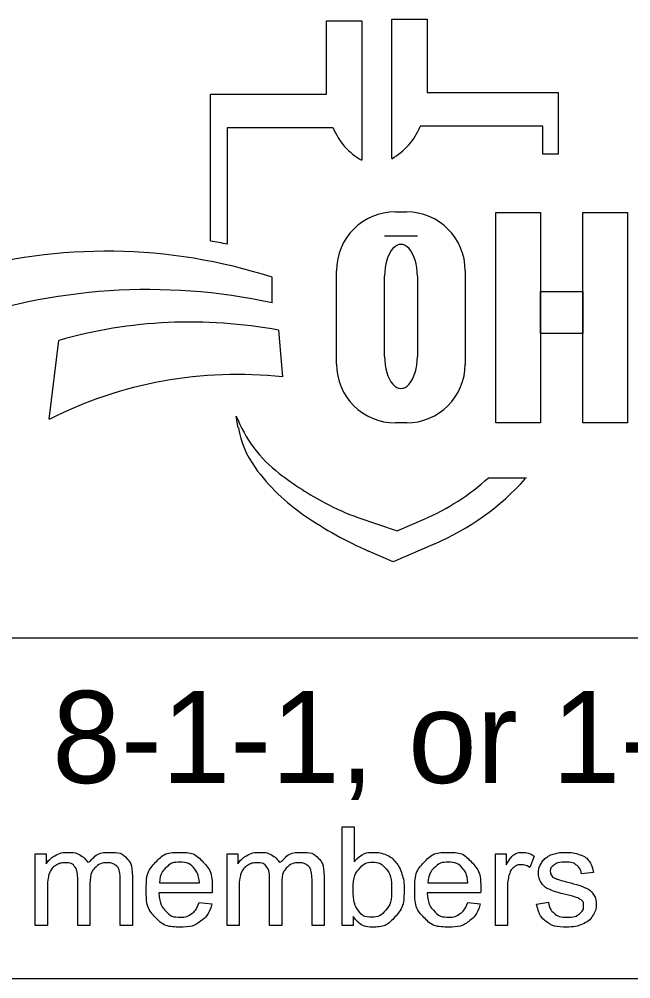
# Model space of a CAD drawing. Extents: x -17.5 to 72.9, y -57.8 to 32.3.
# Drawn here: x -6.937 to -6.007, y 1.809 to 3.269 of the extents above; entities that cross this region are included whole.
import ezdxf

# ---------------------------------------------------------------- set-up
doc = ezdxf.new("R2010")
doc.units = 0
doc.layers.add('SH_Data', color=7, linetype='Continuous')
doc.layers.add('SH_Text', color=7, linetype='Continuous')

msp = doc.modelspace()

# ---------------------------------------------------------------- linework, layer by layer
at = {"layer": 'SH_Data'}
for p, q in [((-3.5759, 2.3272), (-7.8259, 2.3272)), ((-3.5759, 1.8094), (-7.8259, 1.8094))]:
    msp.add_line(p, q, dxfattribs=at)
at = {"layer": 'SH_Text'}
for p, q in [((-6.4699, 3.1549), (-6.4699, 3.2664)), ((-6.4699, 3.2664), (-6.4162, 3.2664)), ((-6.4162, 3.2664), (-6.4162, 3.0543)), ((-6.3705, 3.0566), (-6.3705, 3.2687)), ((-6.3705, 3.2687), (-6.3169, 3.2687)), ((-6.3169, 3.2687), (-6.3169, 3.1572)), ((-6.6458, 2.931), (-6.6458, 3.1549)), ((-6.6458, 3.1549), (-6.4699, 3.1549)), ((-6.3169, 3.1572), (-6.1177, 3.1572)), ((-6.1177, 3.1572), (-6.1177, 3.0634)), ((-6.6206, 3.1034), (-6.6206, 2.9266)), ((-6.4594, 3.1034), (-6.6206, 3.1034)), ((-6.1409, 3.1058), (-6.3273, 3.1058)), ((-6.1409, 3.0634), (-6.1409, 3.1058)), ((-6.1177, 3.0634), (-6.1409, 3.0634)), ((-6.3649, 2.9757), (-6.3483, 2.9757)), ((-6.3316, 2.9387), (-6.3814, 2.9387)), ((-6.5525, 2.8763), (-6.5525, 2.8375)), ((-6.4543, 2.7442), (-6.4543, 2.8862)), ((-6.3814, 2.7556), (-6.3814, 2.8779)), ((-6.3316, 2.8779), (-6.3316, 2.7556)), ((-6.2589, 2.8862), (-6.2589, 2.7442)), ((-6.5426, 2.7957), (-6.5363, 2.7248)), ((-6.8914, 2.6602), (-6.8767, 2.7803)), ((-6.6037, 2.6473), (-6.6067, 2.6652)), ((-6.3483, 2.6547), (-6.3649, 2.6547)), ((-6.2234, 2.5714), (-6.1659, 2.5714)), ((-6.4218, 2.511), (-6.3624, 2.4905)), ((-6.3624, 2.4905), (-6.3213, 2.5083)), ((-6.3051, 2.471), (-6.3684, 2.4435)), ((-6.3684, 2.4435), (-6.4058, 2.4599))]:
    msp.add_line(p, q, dxfattribs=at)
for points in [[(-6.2124, 2.9746), (-6.1445, 2.9746), (-6.1445, 2.6547), (-6.2124, 2.6547)], [(-6.0803, 2.9746), (-6.0123, 2.9746), (-6.0123, 2.6547), (-6.0803, 2.6547)], [(-6.1445, 2.8548), (-6.0803, 2.8548), (-6.0803, 2.7908), (-6.1445, 2.7908)]]:
    msp.add_lwpolyline(points, close=True, dxfattribs=at)
for points in [[(-6.4291, 1.8905), (-6.4461, 1.8905), (-6.4461, 2.0407), (-6.4277, 2.0407), (-6.4277, 1.9871)], [(-6.9122, 1.8905), (-6.9122, 1.9993), (-6.8957, 1.9993), (-6.8957, 1.984)], [(-6.6208, 1.8905), (-6.6208, 1.9993), (-6.6043, 1.9993), (-6.6043, 1.984)], [(-6.213, 1.8905), (-6.213, 1.9993), (-6.1964, 1.9993), (-6.1964, 1.9828)], [(-6.1539, 1.9959), (-6.1604, 1.9788)], [(-6.064, 1.9712), (-6.0821, 1.9688)], [(-6.8291, 1.9537), (-6.8291, 1.8905), (-6.8475, 1.8905), (-6.8475, 1.9611)], [(-6.7646, 1.9652), (-6.7646, 1.8905), (-6.7831, 1.8905), (-6.7831, 1.959)], [(-6.5377, 1.9537), (-6.5377, 1.8905), (-6.5561, 1.8905), (-6.5561, 1.9611)], [(-6.4733, 1.9652), (-6.4733, 1.8905), (-6.4917, 1.8905), (-6.4917, 1.959)], [(-6.8937, 1.9469), (-6.8937, 1.8905), (-6.9122, 1.8905)], [(-6.7235, 1.9553), (-6.6628, 1.9553)], [(-6.6024, 1.9469), (-6.6024, 1.8905), (-6.6208, 1.8905)], [(-6.3155, 1.9553), (-6.2548, 1.9553)], [(-6.1946, 1.9475), (-6.1946, 1.8905), (-6.213, 1.8905)], [(-6.6434, 1.9402), (-6.7246, 1.9402)], [(-6.2354, 1.9402), (-6.3166, 1.9402)], [(-6.663, 1.9256), (-6.6439, 1.9232)], [(-6.255, 1.9256), (-6.2359, 1.9232)], [(-6.1504, 1.923), (-6.1322, 1.9259)], [(-6.4291, 1.9041), (-6.4291, 1.8905)]]:
    msp.add_lwpolyline(points, dxfattribs=at)
for centre, radius, start, end in [((-6.3681, 3.1402), 0.0985, 201.9296, 240.7469), ((-6.4187, 3.1425), 0.0985, 299.2531, 338.0704), ((-6.3649, 2.8862), 0.0895, 90, 180), ((-6.3483, 2.8862), 0.0895, 0, 90), ((-6.7739, 2.122), 0.8191, 79.2074, 81.0007), ((-6.8037, 2.0967), 0.8191, 72.1402, 106.3144), ((-6.7406, 1.9656), 0.8919, 77.8238, 109.8274), ((-6.6767, 2.0759), 0.7322, 79.44, 105.8467), ((-6.3649, 2.7442), 0.0895, 180, 270), ((-6.3483, 2.7442), 0.0895, 270, 0), ((-6.6047, 2.0927), 0.6357, 83.8248, 116.8021), ((-6.4193, 2.7373), 0.2008, 201.0457, 232.5314), ((-6.4624, 2.6714), 0.1433, 189.6817, 216.0884), ((-6.3287, 2.7688), 0.3088, 216.0884, 235.7167), ((-6.2268, 2.9885), 0.5173, 232.5314, 241.794), ((-6.4647, 2.8388), 0.3602, 293.4582, 312.0712), ((-6.4647, 2.8388), 0.401, 293.4582, 317.8286), ((-6.312, 2.8297), 0.3371, 241.794, 250.9821), ((-6.1622, 3.013), 0.6044, 235.7167, 246.2325)]:
    msp.add_arc(centre, radius, start, end, dxfattribs=at)
for centre, start_param, end_param in [((-6.3565, 2.8779), 4.712389, 7.853982), ((-6.3565, 2.7556), 1.570796, 4.712389)]:
    msp.add_ellipse(centre, major_axis=(0, 0.0484), ratio=0.514403, start_param=start_param, end_param=end_param, dxfattribs=at)
for points in [[(-6.8957, 1.984), (-6.8905, 1.992), (-6.882, 1.9969), (-6.8735, 2.0017), (-6.8627, 2.0017), (-6.8506, 2.0017), (-6.8428, 1.9967), (-6.8351, 1.9917), (-6.8319, 1.9826), (-6.819, 2.0017), (-6.7983, 2.0017), (-6.7821, 2.0017), (-6.7734, 1.9928), (-6.7646, 1.9838), (-6.7646, 1.9652)], [(-6.6439, 1.9232), (-6.6484, 1.9065), (-6.6606, 1.8973), (-6.6728, 1.8881), (-6.6917, 1.8881), (-6.7156, 1.8881), (-6.7296, 1.9028), (-6.7436, 1.9175), (-6.7436, 1.944), (-6.7436, 1.9714), (-6.7294, 1.9866), (-6.7153, 2.0017), (-6.6928, 2.0017), (-6.671, 2.0017), (-6.6571, 1.9869), (-6.6433, 1.972), (-6.6433, 1.9451), (-6.6433, 1.9435), (-6.6434, 1.9402)], [(-6.6043, 1.984), (-6.5992, 1.992), (-6.5907, 1.9969), (-6.5822, 2.0017), (-6.5713, 2.0017), (-6.5592, 2.0017), (-6.5515, 1.9967), (-6.5437, 1.9917), (-6.5406, 1.9826), (-6.5276, 2.0017), (-6.5069, 2.0017), (-6.4907, 2.0017), (-6.482, 1.9928), (-6.4733, 1.9838), (-6.4733, 1.9652)], [(-6.4277, 1.9871), (-6.416, 2.0017), (-6.3979, 2.0017), (-6.3879, 2.0017), (-6.3789, 1.9977), (-6.3699, 1.9937), (-6.3642, 1.9863), (-6.3584, 1.979), (-6.3551, 1.9687), (-6.3518, 1.9583), (-6.3518, 1.9466), (-6.3518, 1.9186), (-6.3656, 1.9034), (-6.3795, 1.8881), (-6.3988, 1.8881), (-6.4181, 1.8881), (-6.4291, 1.9041)], [(-6.2359, 1.9232), (-6.2404, 1.9065), (-6.2526, 1.8973), (-6.2648, 1.8881), (-6.2837, 1.8881), (-6.3076, 1.8881), (-6.3216, 1.9028), (-6.3356, 1.9175), (-6.3356, 1.944), (-6.3356, 1.9714), (-6.3214, 1.9866), (-6.3073, 2.0017), (-6.2848, 2.0017), (-6.263, 2.0017), (-6.2491, 1.9869), (-6.2353, 1.972), (-6.2353, 1.9451), (-6.2353, 1.9435), (-6.2354, 1.9402)], [(-6.1964, 1.9828), (-6.1901, 1.9944), (-6.1847, 1.9981), (-6.1793, 2.0017), (-6.1729, 2.0017), (-6.1636, 2.0017), (-6.1539, 1.9959)], [(-6.1322, 1.9259), (-6.1307, 1.9149), (-6.1236, 1.9091), (-6.1166, 1.9032), (-6.1039, 1.9032), (-6.0912, 1.9032), (-6.085, 1.9084), (-6.0789, 1.9136), (-6.0789, 1.9205), (-6.0789, 1.9268), (-6.0843, 1.9304), (-6.0881, 1.9329), (-6.1032, 1.9367), (-6.1235, 1.9418), (-6.1314, 1.9455), (-6.1392, 1.9492), (-6.1433, 1.9558), (-6.1473, 1.9624), (-6.1473, 1.9704), (-6.1473, 1.9777), (-6.144, 1.9839), (-6.1406, 1.9901), (-6.1349, 1.9942), (-6.1306, 1.9973), (-6.1231, 1.9995), (-6.1157, 2.0017), (-6.1072, 2.0017), (-6.0944, 2.0017), (-6.0847, 1.9981), (-6.075, 1.9944), (-6.0704, 1.9881), (-6.0657, 1.9817), (-6.064, 1.9712)], [(-6.8475, 1.9611), (-6.8475, 1.9734), (-6.852, 1.9796), (-6.8565, 1.9857), (-6.8668, 1.9857), (-6.8746, 1.9857), (-6.8812, 1.9816), (-6.8878, 1.9775), (-6.8908, 1.9696), (-6.8937, 1.9618), (-6.8937, 1.9469)], [(-6.7831, 1.959), (-6.7831, 1.9701), (-6.7849, 1.9749), (-6.7866, 1.9798), (-6.7914, 1.9828), (-6.7961, 1.9857), (-6.8024, 1.9857), (-6.8139, 1.9857), (-6.8215, 1.9781), (-6.8291, 1.9705), (-6.8291, 1.9537)], [(-6.6628, 1.9553), (-6.664, 1.9691), (-6.6697, 1.9759), (-6.6785, 1.9866), (-6.6926, 1.9866), (-6.7053, 1.9866), (-6.7139, 1.9781), (-6.7226, 1.9696), (-6.7235, 1.9553)], [(-6.5561, 1.9611), (-6.5561, 1.9734), (-6.5606, 1.9796), (-6.5651, 1.9857), (-6.5754, 1.9857), (-6.5832, 1.9857), (-6.5898, 1.9816), (-6.5964, 1.9775), (-6.5994, 1.9696), (-6.6024, 1.9618), (-6.6024, 1.9469)], [(-6.4917, 1.959), (-6.4917, 1.9701), (-6.4935, 1.9749), (-6.4953, 1.9798), (-6.5, 1.9828), (-6.5047, 1.9857), (-6.5111, 1.9857), (-6.5225, 1.9857), (-6.5301, 1.9781), (-6.5377, 1.9705), (-6.5377, 1.9537)], [(-6.4293, 1.9457), (-6.4293, 1.9262), (-6.424, 1.9175), (-6.4153, 1.9032), (-6.4005, 1.9032), (-6.3884, 1.9032), (-6.3796, 1.9137), (-6.3708, 1.9242), (-6.3708, 1.945), (-6.3708, 1.9663), (-6.3792, 1.9765), (-6.3877, 1.9866), (-6.3996, 1.9866), (-6.4117, 1.9866), (-6.4205, 1.9761), (-6.4293, 1.9656), (-6.4293, 1.9457)], [(-6.2548, 1.9553), (-6.256, 1.9691), (-6.2617, 1.9759), (-6.2706, 1.9866), (-6.2846, 1.9866), (-6.2973, 1.9866), (-6.306, 1.9781), (-6.3146, 1.9696), (-6.3155, 1.9553)], [(-6.0821, 1.9688), (-6.0833, 1.9772), (-6.0892, 1.9819), (-6.0951, 1.9866), (-6.1059, 1.9866), (-6.1186, 1.9866), (-6.124, 1.9824), (-6.1295, 1.9782), (-6.1295, 1.9726), (-6.1295, 1.969), (-6.1272, 1.9661), (-6.1249, 1.9631), (-6.1201, 1.9612), (-6.1174, 1.9602), (-6.1038, 1.9565), (-6.0842, 1.9513), (-6.0765, 1.9479), (-6.0687, 1.9446), (-6.0643, 1.9383), (-6.0599, 1.9319), (-6.0599, 1.9225), (-6.0599, 1.9133), (-6.0653, 1.9051), (-6.0706, 1.897), (-6.0808, 1.8926), (-6.091, 1.8881), (-6.1038, 1.8881), (-6.125, 1.8881), (-6.1362, 1.8969), (-6.1473, 1.9057), (-6.1504, 1.923)], [(-6.1604, 1.9788), (-6.1671, 1.9827), (-6.1739, 1.9827), (-6.1799, 1.9827), (-6.1847, 1.9791), (-6.1895, 1.9755), (-6.1915, 1.969), (-6.1946, 1.9592), (-6.1946, 1.9475)], [(-6.7246, 1.9402), (-6.7235, 1.9223), (-6.7144, 1.9127), (-6.7053, 1.9032), (-6.6917, 1.9032), (-6.6815, 1.9032), (-6.6743, 1.9086), (-6.6672, 1.9139), (-6.663, 1.9256)], [(-6.3166, 1.9402), (-6.3155, 1.9223), (-6.3064, 1.9127), (-6.2973, 1.9032), (-6.2837, 1.9032), (-6.2735, 1.9032), (-6.2664, 1.9086), (-6.2592, 1.9139), (-6.255, 1.9256)]]:
    msp.add_open_spline(points, degree=3, dxfattribs=at)

# ---------------------------------------------------------------- texts
msp.add_text('OHIO811, 8-1-1, or 1-800-362-2764', height=0.14, dxfattribs=at).set_placement((-7.7814, 2.1072))

doc.saveas('drawing.dxf')
